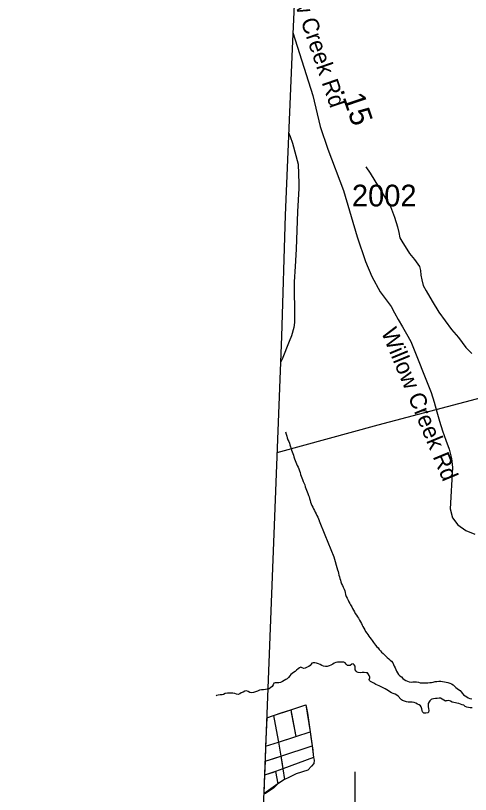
# Model space of a CAD drawing. Extents: x 1662474 to 1856135, y 779280 to 917889.
# Drawn here: x 1691457 to 1694071, y 863425 to 867907 of the extents above; entities that cross this region are included whole.
import ezdxf

# ---------------------------------------------------------------- set-up
doc = ezdxf.new("R2010")
doc.units = 0
for name, color, linetype in [('Exist Boundary Political CountyLine', 7, 'Continuous'), ('Exist Hydrographic Creek Single Shore', 7, 'Continuous'), ('Exist Hydrographic Misc Water Feature', 7, 'Continuous'), ('Exist Road Non-System Type 51', 7, 'Continuous'), ('Exist Road Non-System Type 51 Label', 7, 'Continuous'), ('Exist Road Secondary Mileage Tenths English Label', 7, 'Continuous'), ('Exist Road Secondary Type 20 Attributed', 7, 'Continuous'), ('Exist Road Secondary Type 51 Attributed', 7, 'Continuous'), ('Exist Road Secondary Type 51 Label', 7, 'Continuous'), ('Exist Road Secondary Type 51 Number Label', 7, 'Continuous'), ('Exist Utilities Electrical Transmission Line', 7, 'Continuous')]:
    doc.layers.add(name, color=color, linetype=linetype)

msp = doc.modelspace()

# ---------------------------------------------------------------- linework, layer by layer
at = {"layer": 'Exist Boundary Political CountyLine'}
msp.add_lwpolyline([(1693532.8, 878638.3), (1693519.9, 877349.9), (1693492, 876609.6), (1693453.8, 875667.6), (1693430.2, 875135.3), (1693375.3, 874115.3), (1693330.7, 873313.6), (1693283.8, 872475.6), (1693250.6, 871813.5), (1693208.1, 871017.3), (1693160.5, 870131.4), (1693122.4, 869369.3), (1693086.5, 868609.1), (1693046.7, 867715.1), (1693006.5, 866759), (1692985.5, 866061), (1692761.5, 860283.7), (1692552.7, 854372.1), (1692258.3, 846140.6), (1691699.3, 830912), (1691456.7, 824436.5)], dxfattribs=at)
at = {"layer": 'Exist Hydrographic Creek Single Shore'}
for points in [[(1693007.8, 865511.1), (1693011.6, 865497.4), (1693015.4, 865487.7), (1693018.8, 865477.2), (1693022.4, 865466.4), (1693026.9, 865456.2), (1693031.1, 865446.8), (1693033.4, 865437.1), (1693036.4, 865426.2), (1693040.2, 865416.8), (1693043.6, 865406.9), (1693047.4, 865397.4), (1693050.8, 865387.9), (1693053.9, 865376.7), (1693056.5, 865367.5), (1693059.9, 865356.8), (1693063.9, 865347.6), (1693067.8, 865337.1), (1693072, 865327.9), (1693076.2, 865318.7), (1693080.9, 865308.7), (1693085.9, 865297.9), (1693088.2, 865287.7), (1693092, 865278.2), (1693095.4, 865267), (1693099, 865257), (1693102.8, 865247.3), (1693106.9, 865237.1), (1693110.9, 865226.8), (1693114.2, 865217.4), (1693118.8, 865206.6), (1693122.4, 865196.1), (1693124.8, 865185.4), (1693128.8, 865175.6), (1693132.6, 865165.9), (1693136.2, 865155.9), (1693140, 865146), (1693143.6, 865137.1), (1693147.1, 865127.6), (1693150.2, 865116.9), (1693152.4, 865106.9), (1693155.8, 865097.2), (1693160.2, 865088), (1693164.6, 865078.2), (1693169.6, 865068.3), (1693175.1, 865059.4), (1693179.6, 865049.9), (1693184.1, 865039.9), (1693189, 865030.8), (1693193.5, 865020.5), (1693197.2, 865010.6), (1693201.9, 865000.6), (1693202.1, 865000.1), (1693234.5, 864919.8), (1693285.6, 864793), (1693306.6, 864718.4), (1693310.4, 864708.2), (1693313.2, 864698.5), (1693315.9, 864687.2), (1693318.1, 864678.1), (1693321.6, 864667.8), (1693324.5, 864658.6), (1693327.4, 864647.9), (1693331, 864637.4), (1693335.8, 864626.9), (1693339.8, 864617.1), (1693345, 864606.9), (1693348.9, 864596.4), (1693351.5, 864586.2), (1693354.1, 864575.1), (1693357.9, 864564.9), (1693363.4, 864554.1), (1693368.9, 864543.7), (1693372.8, 864533.7), (1693377.8, 864524.2), (1693382.8, 864515.1), (1693389.2, 864505.3), (1693393.8, 864495.1), (1693398.5, 864485.6), (1693404.2, 864475.4), (1693409.8, 864466), (1693416.1, 864456), (1693421.6, 864447.6), (1693427.4, 864438.9), (1693433.4, 864428.7), (1693438.6, 864419), (1693444.4, 864408.8), (1693449.4, 864399.8), (1693453.9, 864391.2), (1693458.9, 864381.4), (1693464.6, 864371.8), (1693469.1, 864362.6), (1693475.4, 864353.4), (1693481.8, 864344.4), (1693487.5, 864336.1), (1693493, 864328.4), (1693500.1, 864319), (1693506.4, 864310.1), (1693513.5, 864300.1), (1693519.8, 864292.5)], [(1693519.8, 864292.5), (1693526.2, 864283.8), (1693533.1, 864275.2), (1693540.2, 864267.8), (1693547.6, 864259.2), (1693554.1, 864251.3), (1693561.2, 864243.1), (1693569.1, 864235.2), (1693577.2, 864227.7), (1693585.1, 864220.8), (1693593.5, 864213.2), (1693601.9, 864205.1), (1693609.8, 864198), (1693617.9, 864191.4), (1693624.5, 864182.5), (1693628.6, 864173.6), (1693633.1, 864163.4), (1693637.9, 864153.9), (1693642.4, 864143.4), (1693646.5, 864133.4), (1693651.5, 864124.8), (1693658, 864115.9), (1693666.5, 864108), (1693674.9, 864101.7), (1693683.2, 864093), (1693691.1, 864086.5), (1693700, 864080.4), (1693709, 864077.6), (1693719, 864073.4), (1693730, 864070.4), (1693740.5, 864072.3), (1693751, 864072.8), (1693762.2, 864072.1), (1693773, 864070.4), (1693783, 864067.6), (1693793.8, 864067.1), (1693804.8, 864067.1), (1693815.8, 864067.1), (1693826.9, 864067.3), (1693837.9, 864068.1), (1693847, 864069.7), (1693858.2, 864071.8), (1693869.4, 864074.1), (1693879, 864075.4), (1693889.2, 864076), (1693900.9, 864076.2), (1693910.8, 864074.9), (1693921.9, 864072.8), (1693932, 864070.8), (1693942, 864068.6), (1693953, 864065.5), (1693963.5, 864061.8), (1693971.8, 864056), (1693979.5, 864048.1), (1693987.4, 864041.1), (1693995.2, 864035), (1694003.1, 864029.2), (1694012.4, 864023.5), (1694019.2, 864015.9), (1694025.8, 864006.7), (1694032.6, 863998), (1694040.8, 863991.4), (1694050.1, 863985.9), (1694059.4, 863980.9), (1694068.2, 863977.3), (1694078.8, 863975.4)], [(1693350.8, 864181.5), (1693343.1, 864185.7), (1693330.8, 864186.2), (1693319.2, 864186.2), (1693308.2, 864185.9), (1693296.9, 864184.6), (1693287.8, 864180.2), (1693279.6, 864174.6), (1693269.6, 864168.9), (1693259.6, 864164.7), (1693248.4, 864161.8), (1693238.1, 864161.8), (1693226.6, 864162.6), (1693217.6, 864166.5), (1693208.2, 864172.6), (1693197.8, 864177.2), (1693187.2, 864180.4), (1693177.5, 864182), (1693167, 864182.2), (1693159.6, 864180.9), (1693155.5, 864174.9), (1693150, 864166.8), (1693142.6, 864161), (1693133.1, 864156.8), (1693122.4, 864151.8), (1693114.2, 864150.5), (1693104.2, 864154.2), (1693096.6, 864156.6), (1693089.6, 864154.2), (1693080.9, 864147.6), (1693072.5, 864140.6), (1693063.1, 864132.1), (1693054.1, 864126.4), (1693046, 864121.6), (1693038.4, 864114.3), (1693032.6, 864107.8), (1693025.9, 864098.6), (1693018.5, 864089.6), (1693011.1, 864085.7), (1693000.6, 864080.4), (1692990.9, 864074.1), (1692980.4, 864068.9), (1692969.9, 864066.2), (1692960, 864066.2), (1692948.1, 864066.8), (1692940.8, 864064.9), (1692937.4, 864054.7), (1692932.1, 864045.8), (1692924.8, 864040), (1692914.2, 864033.4), (1692903.5, 864030.3), (1692893.2, 864028.8), (1692881, 864027.7), (1692869.6, 864026.9), (1692858.1, 864024.2), (1692846.9, 864019.2), (1692835.5, 864014.8), (1692824.8, 864010.9), (1692813.5, 864009.8), (1692804, 864011.4), (1692793.8, 864016.4), (1692784.6, 864020.3), (1692774.1, 864018.5), (1692764.1, 864014.1), (1692753.6, 864009.1), (1692745.8, 864003.6), (1692736.6, 864000.4), (1692726.6, 864001.7), (1692716.9, 864005.1), (1692705.9, 864006.9), (1692696.8, 864006.9), (1692686, 864006.9), (1692674.4, 864006.9), (1692662.4, 864004.9), (1692652.1, 864000.6), (1692643.8, 863998.8), (1692633.2, 863997.8), (1692621.9, 863995.7), (1692611.4, 863993.3), (1692609.2, 863993.1)], [(1694080.6, 863922.9), (1694070.4, 863924), (1694060.4, 863925.9), (1694050.1, 863927.7), (1694042, 863931.4), (1694032.9, 863937.7), (1694024.5, 863940.6), (1694013.6, 863943.7), (1694004, 863948.4), (1693993.5, 863950.5), (1693986.1, 863951.8), (1693976.4, 863953.1), (1693966.5, 863956.8), (1693956.8, 863961.6), (1693948.1, 863964.7), (1693938.4, 863964.4), (1693930.8, 863962.9), (1693928.9, 863961), (1693918.4, 863967.1), (1693909.5, 863973.9), (1693900, 863978.9), (1693892.1, 863979.6), (1693880.4, 863977.8), (1693870.1, 863976.5), (1693859.9, 863974.9), (1693849.4, 863973.4), (1693845.5, 863970.4), (1693838.1, 863962.6), (1693833.4, 863958.6), (1693828.9, 863948.7), (1693829.1, 863938.7), (1693829.5, 863928.5), (1693830.5, 863918.5), (1693831.5, 863907.2), (1693830, 863898.6), (1693825.8, 863894.6), (1693815, 863891.8), (1693804.5, 863893.3), (1693796.9, 863899.6), (1693793.5, 863908), (1693791.9, 863917.7), (1693789.2, 863928.2), (1693784.5, 863934.2), (1693776.8, 863939.8), (1693766.5, 863945.2), (1693757.2, 863950.8), (1693747.2, 863954.7), (1693736.5, 863956.3), (1693724.8, 863956.6), (1693713.8, 863956.8), (1693704, 863958.4), (1693693.2, 863961.6), (1693681.4, 863964.7), (1693675.4, 863968.4), (1693672.2, 863972.8), (1693657, 863990.4), (1693647.5, 863996.4), (1693638.6, 864001.2), (1693627.4, 864005.4), (1693617.1, 864010.1), (1693609, 864014.6), (1693600.4, 864021.1), (1693591.1, 864026.4), (1693581.1, 864032.1), (1693569.9, 864037.9), (1693559.1, 864043.7), (1693546.5, 864049.2), (1693536.5, 864053.1), (1693527.1, 864058.4), (1693517.1, 864064.7), (1693507.6, 864069.4), (1693497.8, 864074.9), (1693491.9, 864080.4), (1693489.6, 864087.2), (1693492.8, 864095.1), (1693493.8, 864100.6), (1693489.2, 864109.1), (1693483.5, 864119.8), (1693479.9, 864124), (1693471.2, 864125.6), (1693460.8, 864126.6), (1693449.4, 864126.1), (1693438.1, 864125.6), (1693427.1, 864125.8), (1693420.8, 864127.9), (1693414, 864134.5), (1693409.2, 864142.4), (1693409.2, 864153.1), (1693408.8, 864162.3), (1693403.5, 864170.4), (1693396.6, 864175.7), (1693388.8, 864173.9), (1693379.9, 864167.3), (1693375.1, 864166.5), (1693365.4, 864167.6), (1693358.1, 864173.9), (1693350.8, 864181.5)]]:
    msp.add_lwpolyline(points, dxfattribs=at)
at = {"layer": 'Exist Hydrographic Misc Water Feature'}
for p, q in [((1693039.1, 863911.7), (1693125, 863940.3)), ((1693039.1, 863911.7), (1693125, 863940.3)), ((1693125, 863940.3), (1693149.3, 863785.5)), ((1692900.4, 863865.4), (1692938.7, 863878.5)), ((1692900.4, 863865.4), (1692938.7, 863878.5)), ((1692938.7, 863878.5), (1693039.1, 863911.7)), ((1692938.7, 863878.5), (1692967.3, 863726.1)), ((1693039.1, 863911.7), (1693068.7, 863759.2)), ((1692900.4, 863865.4), (1692894, 863702.2)), ((1693068.7, 863759.2), (1693149.3, 863785.5)), ((1693068.7, 863759.2), (1693149.3, 863785.5)), ((1693149.3, 863785.5), (1693161.6, 863704)), ((1692967.3, 863726.1), (1693068.7, 863759.2)), ((1692894, 863702.2), (1692890.7, 863616.4)), ((1692894, 863702.2), (1692967.3, 863726.1)), ((1692894, 863701.8), (1692967.3, 863726.1)), ((1692967.3, 863726.1), (1692981.7, 863645.3)), ((1692967.3, 863726.1), (1692981.7, 863645.3)), ((1692981.7, 863645.3), (1693161.6, 863704)), ((1692981.7, 863645.3), (1693161.6, 863704)), ((1693161.6, 863704), (1693170.1, 863637.4)), ((1692890.7, 863616.7), (1692981.7, 863645.3)), ((1692981.7, 863645.3), (1692993.4, 863572.9)), ((1692890.7, 863616.4), (1692887.6, 863535.3)), ((1693170.1, 863637.4), (1692993.4, 863572.9)), ((1693170.1, 863637.4), (1692993.4, 863572.9)), ((1692950.3, 863556.5), (1692887.6, 863535.3)), ((1692993.4, 863572.9), (1692950.3, 863556.5)), ((1692993.4, 863572.9), (1692950.3, 863556.5)), ((1692950.3, 863556.5), (1692963.7, 863484.9)), ((1692950.3, 863556.5), (1692963.7, 863484.9)), ((1692993.4, 863572.9), (1693002.7, 863510.3)), ((1692993.4, 863572.9), (1693002.7, 863510.3)), ((1692887.6, 863535.3), (1692883.4, 863427.4)), ((1692963.7, 863484.9), (1692883.4, 863427.4)), ((1693002.7, 863510.3), (1692963.7, 863484.9))]:
    msp.add_line(p, q, dxfattribs=at)
for points in [[(1693026.5, 867234.1), (1693035.8, 867210.7), (1693047.9, 867172.7), (1693080.4, 867052.3), (1693084.9, 866940.6), (1693084.7, 866912.6), (1693077.3, 866780.7), (1693070, 866562.6), (1693068.2, 866530.6), (1693064.3, 866464.2), (1693058.9, 866374.1), (1693059.5, 866162.4), (1693059.3, 866140.1), (1693055.5, 866112.3), (1693043.8, 866064.1)], [(1693470.4, 867036.1), (1693494.6, 866999.6), (1693611.3, 866808.4), (1693635.5, 866746.3), (1693651.6, 866691.9), (1693659.7, 866658.1), (1693665.9, 866628.4), (1693677.9, 866608.4), (1693722.1, 866538.6), (1693750.2, 866504.4), (1693778.5, 866462.8), (1693784.5, 866440.5), (1693786.7, 866412.6), (1693792.7, 866386.2), (1693800.5, 866354), (1693816.8, 866322.5), (1693851.1, 866264.4), (1693889.2, 866200.4), (1693963.5, 866100.4), (1694002.6, 866053.7)], [(1693043.8, 866064.1), (1693030.4, 866031.5), (1692988.4, 865929.9), (1692979.6, 865910.3)], [(1694002.6, 866053.7), (1694044.8, 865997), (1694080.1, 865961.8)], [(1693125, 863940.3), (1693134.2, 863892.5), (1693149.3, 863785.5)], [(1692938.7, 863878.5), (1692983.7, 863894), (1693039.1, 863911.7)], [(1692938.7, 863878.5), (1692949.1, 863828.2), (1692967.3, 863726.1)], [(1693039.1, 863911.7), (1693041.8, 863896.9), (1693068.7, 863759.2)], [(1693149.3, 863785.5), (1693153.6, 863754.3), (1693161.6, 863704)], [(1692967.3, 863726.1), (1693056.6, 863754.6), (1693068.7, 863759.2)], [(1693161.6, 863704), (1693165.2, 863680.2), (1693167, 863652.3), (1693170.1, 863637.4)], [(1692890.7, 863616.4), (1692941.5, 863632.2), (1692981.7, 863645.3)], [(1692981.7, 863645.3), (1692987.2, 863613.2), (1692993.4, 863572.9)], [(1693170.1, 863637.4), (1693172.9, 863622.6), (1693170.8, 863602.1), (1693158.8, 863586.8), (1693136.6, 863564.2), (1693070.5, 863542.6), (1693028.2, 863522.9), (1693002.7, 863510.3)], [(1693170.1, 863637.4), (1693172.9, 863622.6), (1693170.8, 863602.1), (1693158.8, 863586.8), (1693136.6, 863564.2), (1693070.5, 863542.6), (1693028.2, 863522.9), (1693002.7, 863510.3)], [(1692950.3, 863556.5), (1692936.7, 863551.9), (1692887.6, 863535.3)], [(1692963.7, 863484.9), (1692942, 863463.1), (1692909.7, 863441.6), (1692893.6, 863429.6), (1692883.4, 863427.4)], [(1693002.7, 863510.3), (1692996.1, 863507.2), (1692970.2, 863491.3), (1692963.7, 863484.9)]]:
    msp.add_lwpolyline(points, dxfattribs=at)
at = {"layer": 'Exist Road Non-System Type 51'}
msp.add_lwpolyline([(1693341.2, 866900.7), (1693420, 866634.1), (1693468.4, 866491.1), (1693504, 866406), (1693552.6, 866317.9), (1693615.2, 866232.4), (1693635.1, 866197.2), (1693656.9, 866157.9), (1693680.2, 866116.4), (1693704.6, 866075.6), (1693728.1, 866032.4), (1693845.8, 865737.5), (1693862.9, 865683), (1693878.8, 865627.6), (1693894.4, 865572.2), (1693911.9, 865517.4), (1693930.6, 865463.8), (1693948.5, 865412.4), (1693962, 865359.1), (1693968.6, 865306.2), (1693954.5, 865068.2), (1693968.6, 865016.7), (1693999.6, 864975.9), (1694044.5, 864944.4), (1694096.2, 864923)], dxfattribs=at)
at = {"layer": 'Exist Road Secondary Type 20 Attributed'}
msp.add_lwpolyline([(1693050.7, 867809.2), (1693165.5, 867447.3), (1693207.8, 867269.6), (1693251.8, 867137.6), (1693341.2, 866900.7)], dxfattribs=at)
at = {"layer": 'Exist Road Secondary Type 51 Attributed'}
msp.add_lwpolyline([(1693149.5, 862815.5), (1693287.6, 862803.7), (1693310.2, 862805.5), (1693329.2, 862809.9), (1693349.4, 862816.1), (1693364.5, 862822.4), (1693384.8, 862834.2), (1693397.7, 862849.4), (1693403.9, 862897.1), (1693408.1, 863150.5), (1693408.1, 863555.6)], dxfattribs=at)
at = {"layer": 'Exist Utilities Electrical Transmission Line'}
msp.add_lwpolyline([(1692959.6, 865393.2), (1693540.2, 865551.8), (1694505.4, 865807.2), (1694938.9, 865928.7), (1695331.1, 866033.2), (1695885.7, 866211.3), (1696344.9, 866338.5)], dxfattribs=at)

# ---------------------------------------------------------------- texts
at = {"layer": 'Exist Road Non-System Type 51 Label'}
msp.add_text('Willow Creek Rd', height=95, rotation=292.473, dxfattribs=at).set_placement((1693556.8, 866087.1))
at = {"layer": 'Exist Road Secondary Mileage Tenths English Label'}
msp.add_text('.15', height=125, rotation=288.8418, dxfattribs=at).set_placement((1693320.9, 867483.1))
at = {"layer": 'Exist Road Secondary Type 51 Label'}
for s, rotation, p in [('Crosscreek Rd', 333.0307, (1693917.7, 868241.7)), ('Willow Creek Rd', 288.8561, (1692964.4, 868258))]:
    msp.add_text(s, height=95, rotation=rotation, dxfattribs=at).set_placement(p)
at = {"layer": 'Exist Road Secondary Type 51 Number Label'}
msp.add_text('2002', height=125, dxfattribs=at).set_placement((1693390.1, 866809.1))

doc.saveas('drawing.dxf')
